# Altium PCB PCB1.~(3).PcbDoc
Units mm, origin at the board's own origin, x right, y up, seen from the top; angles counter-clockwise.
Board outline 152.4 x 101.6 mm, 2 copper layers (Top Layer, Bottom Layer); 27 components, 22 nets, 77 pads, 0 vias.
Unrouted connection lines stored in the file: 50.
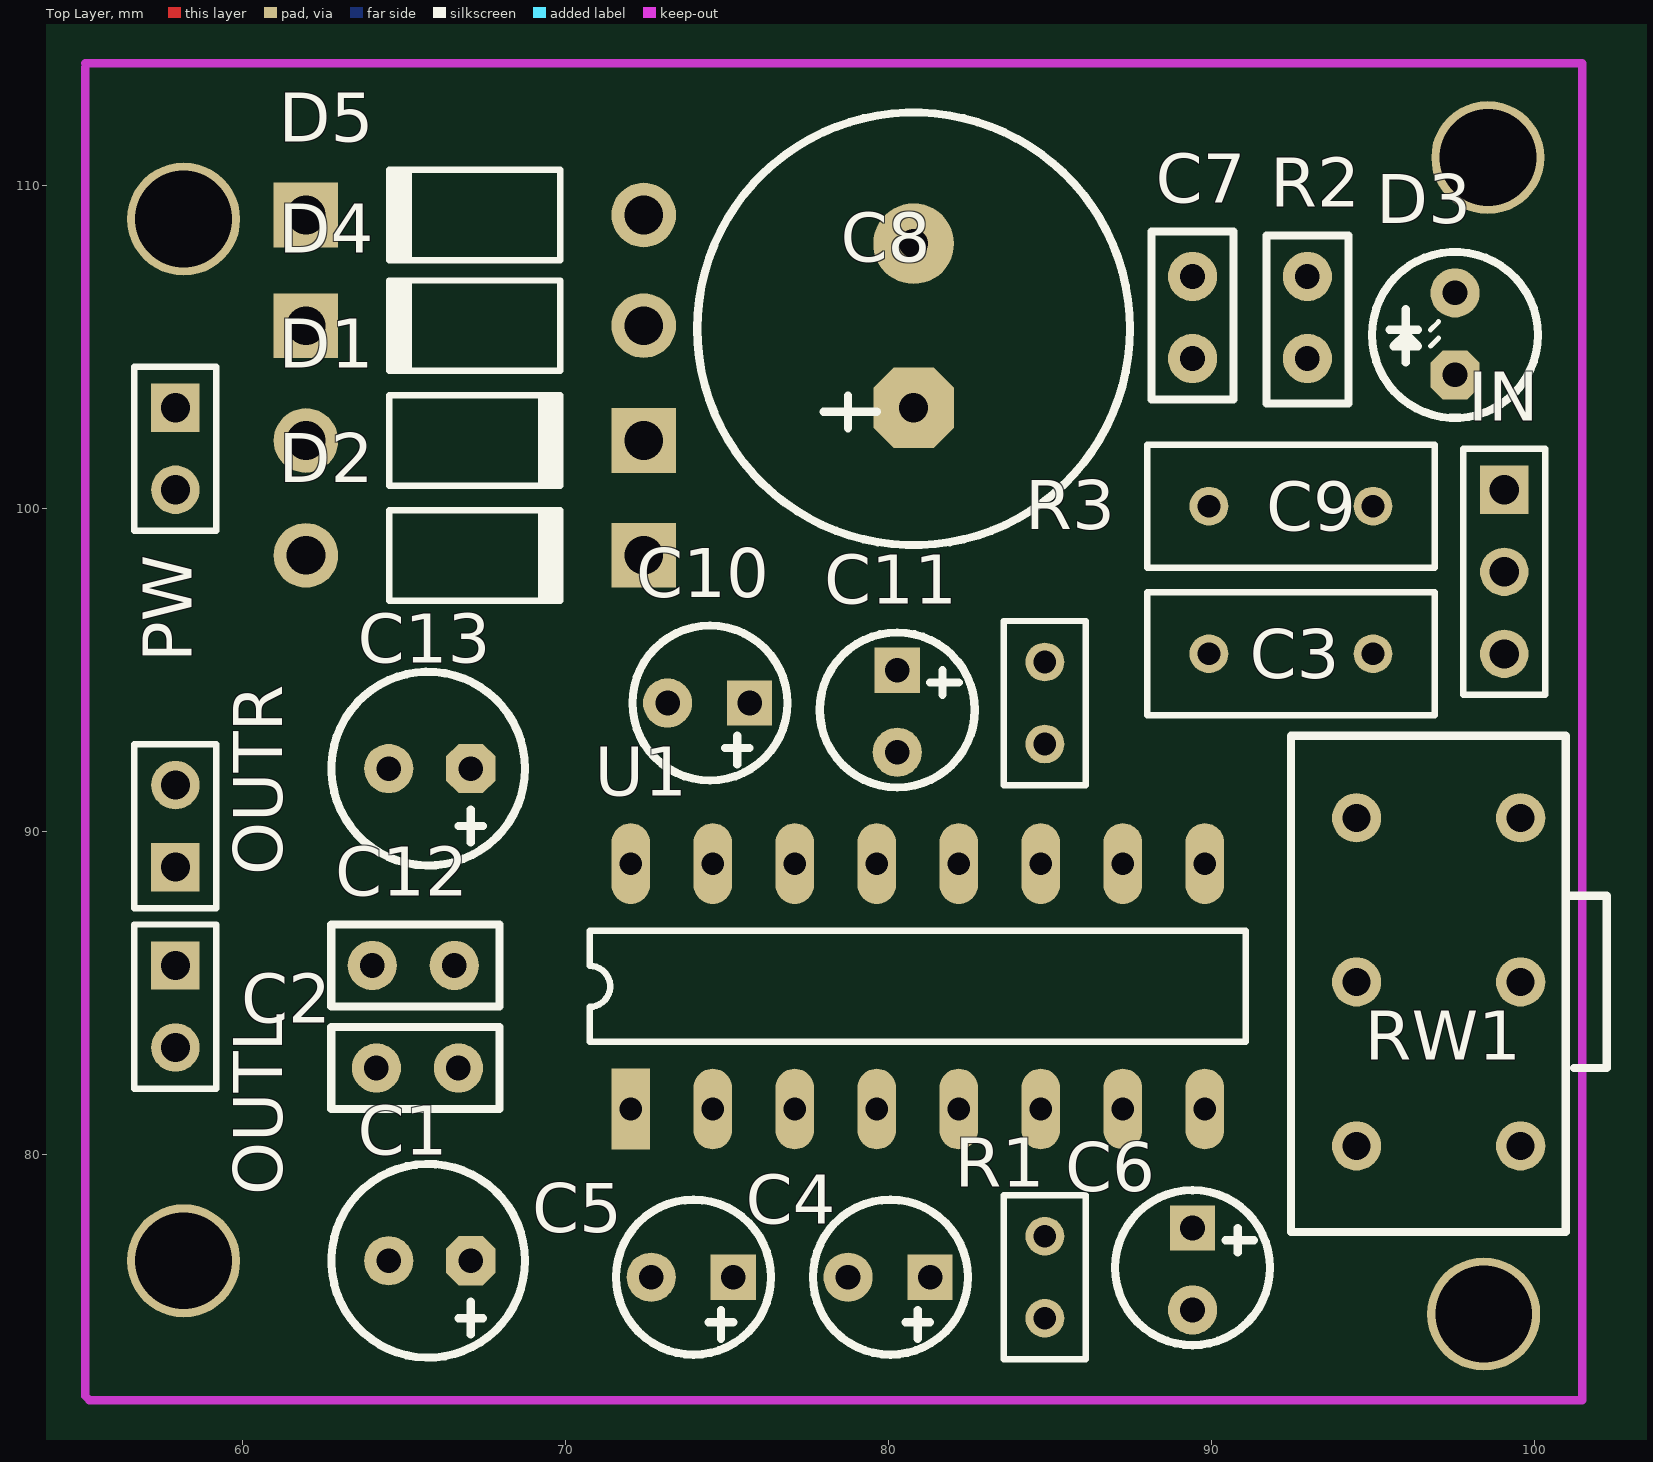
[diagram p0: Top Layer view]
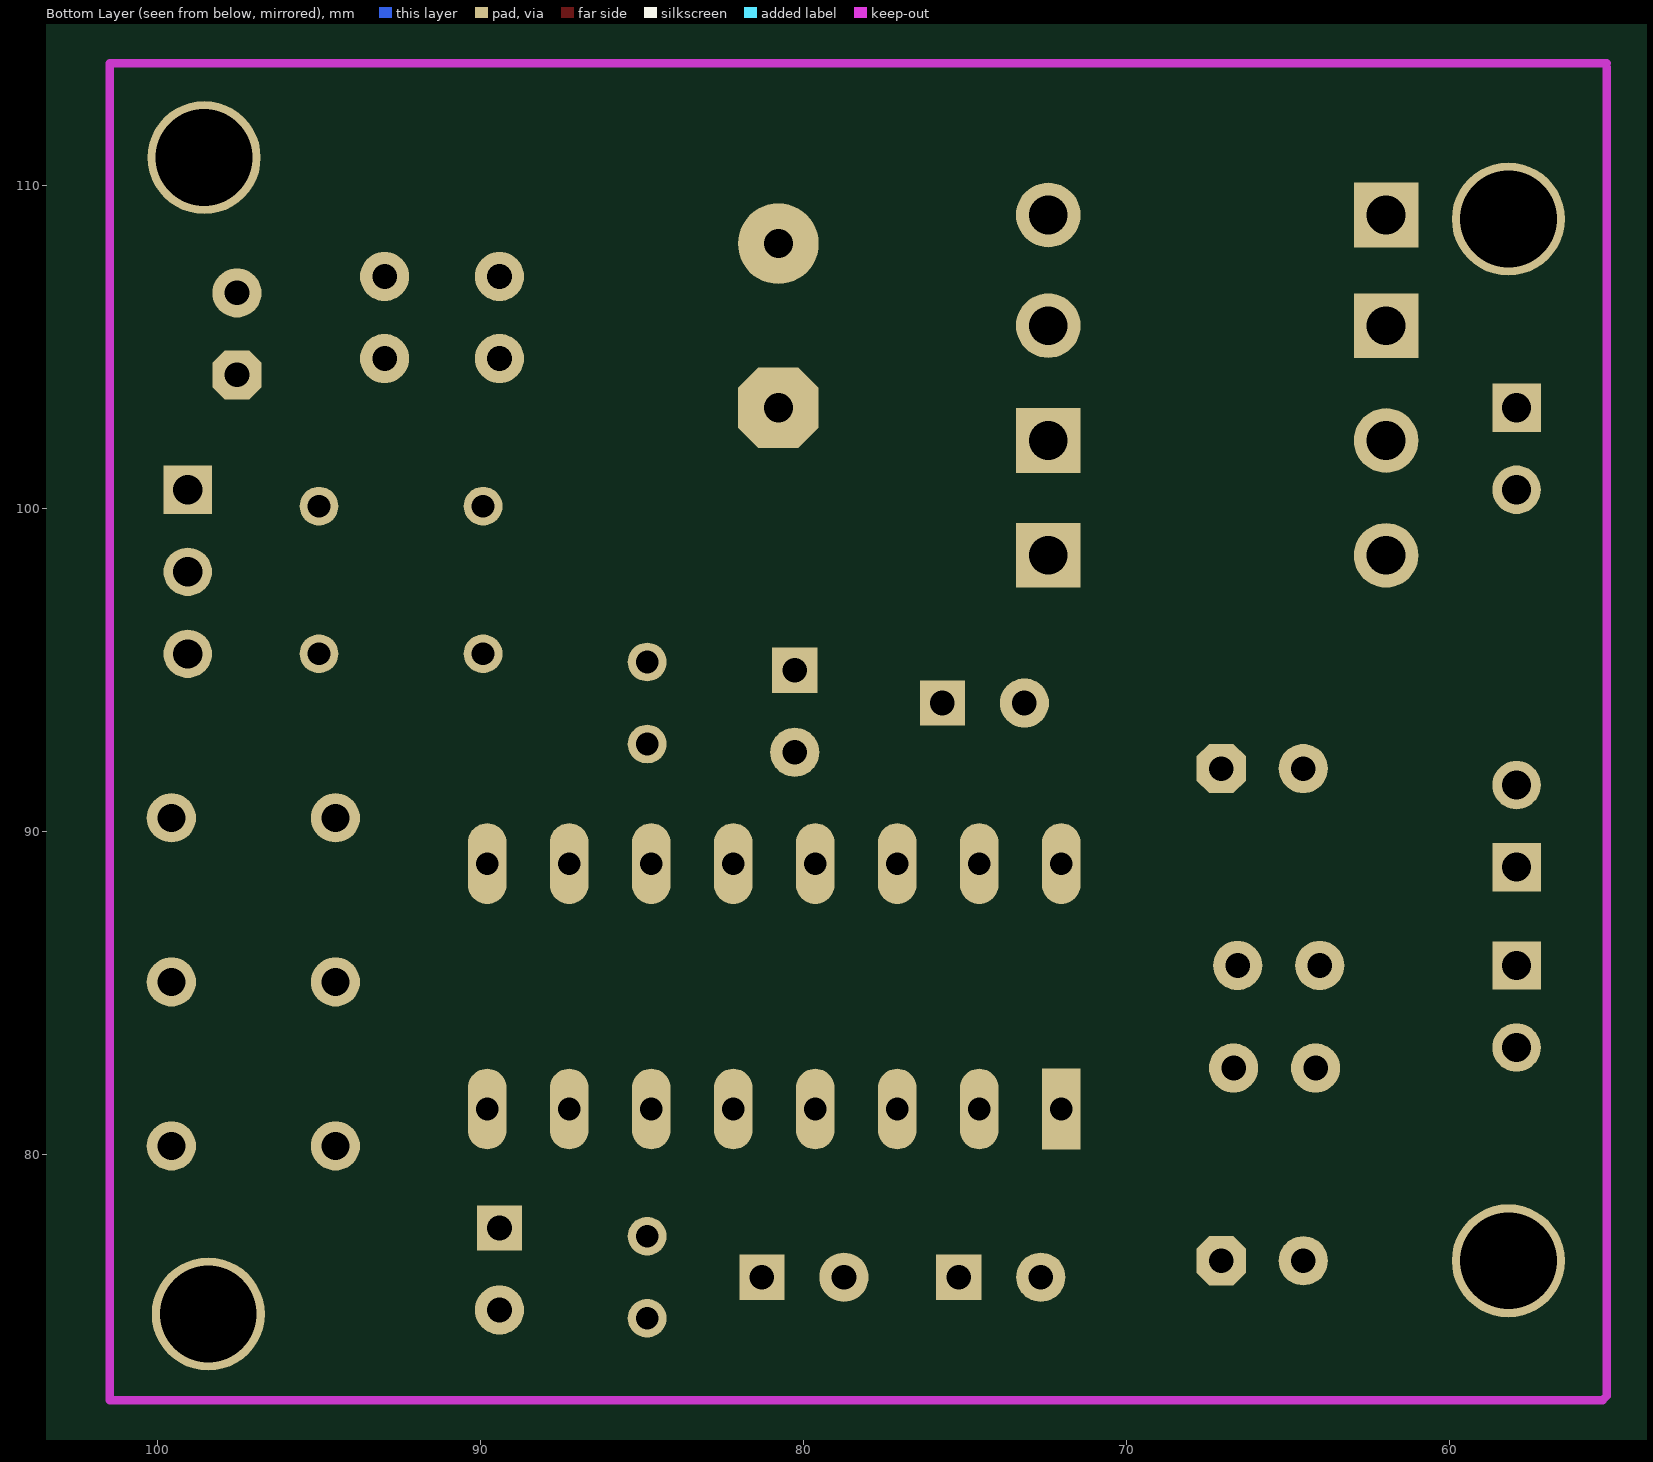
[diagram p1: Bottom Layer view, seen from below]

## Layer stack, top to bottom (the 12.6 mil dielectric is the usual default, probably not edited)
Top Layer: signal copper 0.0356
Dielectric: dielectric 0.32, FR-4, Dk 4.8
Bottom Layer: signal copper 0.0356

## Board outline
25.4,25.4 177.8,25.4 177.8,127 25.4,127

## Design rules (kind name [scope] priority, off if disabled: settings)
Clearance [All] p1: gap=0.254
PolygonConnect [All] p1: connectstyle=Relief reliefconductorwidth=0.254 reliefentries=4 polygonreliefangle="90 Angle"
RoutingVias [All] p1: holewidth=0.711 width=1.27 viastyle="Through Hole" minholewidth=0.711 minwidth=1.27 maxholewidth=0.711 maxwidth=1.27
SilkscreenOverComponentPads [All] p1: minsilkscreentomaskgap=0.254
SolderMaskExpansion [All] p1: expansion=0.102
Width [All] p1: maxlimit=0.254 minlimit=0.254 preferedwidth=0.254
27 further rules are at their usual default settings.

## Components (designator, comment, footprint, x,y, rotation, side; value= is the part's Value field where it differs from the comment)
C1 "470u" CF0.1-6.5 67.056,76.708 r180 top
C2 "0.1u" RAD0.1 64.135,82.677 r0 top
C3 "0.22" RAD-0.2 92.456,95.504 r180 top
C4 "100u" CF0.1 81.28,76.2 r180 top
C5 "100u" CF0.1 75.184,76.2 r180 top
C6 "100u" CF0.1 89.408,77.724 r270 top
C7 "Cap" RAD0.1 89.408,107.188 r270 top
C8 "CF" CF0.2-13 80.772,103.124 r90 top
C9 "0.22" RAD-0.2 92.456,100.076 r180 top
C10 "100u" CF0.1 75.692,93.98 r180 top
C11 "100u" CF0.1 80.264,94.996 r270 top
C12 "0.1u" RAD0.1 66.548,85.852 r180 top
C13 "470u" CF0.1-6.5 67.056,91.948 r180 top
D1 "Diode 1N4007" DIO10.46-5.3x2.8 67.183,102.108 r0 top
D2 "Diode 1N4007" DIO10.46-5.3x2.8 67.183,98.552 r0 top
D3 "LED0" LED 97.536,104.14 r90 top
D4 "Diode 1N4007" DIO10.46-5.3x2.8 67.183,105.664 r180 top
D5 "Diode 1N4007" DIO10.46-5.3x2.8 67.183,109.093 r180 top
IN "" HDR1X3 99.06,100.584 r270 top
OUTL "Header 2" HDR1X2 57.912,85.852 r270 top
OUTR "Header 2" HDR1X2 57.912,88.9 r90 top
PW "Header 2" HDR1X2 57.912,103.124 r270 top
R1 "1k" RAD-0.1 84.836,76.2 r270 top
R2 "Res" RAD0.1 92.964,104.648 r90 top
R3 "1k" RAD-0.1 84.836,93.98 r270 top
RW1 "RW" RW 99.568,80.264 r180 top
U1 "TEA2025" DIP16 72.009,81.407 r90 top

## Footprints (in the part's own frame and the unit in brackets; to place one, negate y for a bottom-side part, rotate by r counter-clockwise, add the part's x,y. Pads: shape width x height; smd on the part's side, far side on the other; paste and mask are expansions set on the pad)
CF0.1 [mil]
  rect 55.12x55.12 hole 30: 1(0,0)
  round 60 hole 30: 2(100,0)
  silkscreen extent -46,-94 143,94
CF0.1-6.5 [mil]
  oct 60x60 hole 30: 1(0,0)
  round 60 hole 30: 2(100,0)
  silkscreen extent -66,-118 170,118
CF0.2-13 [mm]
  oct 2.5x2.5 hole 0.9: 1(0,0)
  round 2.5 hole 0.9: 2(5.08,0)
  silkscreen extent -4.25,-6.7 9.14,6.7
DIO10.46-5.3x2.8 [mm] "Diode, Axial; Body 5.2 x 2.7 mm (LxDia. max), Lead Dia. 0.86 mm (max)"
  round 2 hole 1.2: 1(-5.23,0)
  rect 2x2 hole 1.2: 2(5.23,0)
  silkscreen extent -2.65,-1.4 2.75,1.4
DIP16 [mm]
  rect 2.5x1.2 hole 0.7: 1(0,0)
  oval 2.5x1.2 hole 0.7: 2(0,-2.54) 3(0,-5.08) 4(0,-7.62) 5(0,-10.16) 6(0,-12.7) 7(0,-15.24) 8(0,-17.78) 9(7.6,-17.78) 10(7.6,-15.24) 11(7.6,-12.7) 12(7.6,-10.16) 13(7.6,-7.62) 14(7.6,-5.08) 15(7.6,-2.54) 16(7.6,0)
  silkscreen extent 2.08,-19.05 5.52,1.27
HDR1X2 [mm] "Connector; Header; 2 Position"
  rect 1.5x1.5 hole 0.9: 1(0,0)
  round 1.5 hole 0.9: 2(2.54,0)
  silkscreen extent -1.27,-1.27 3.81,1.27
HDR1X3 [mm] "Connector; Header; 3 Position"
  rect 1.5x1.5 hole 0.9: 1(0,0)
  round 1.5 hole 0.9: 2(2.54,0) 3(5.08,0)
  silkscreen extent -1.27,-1.27 6.35,1.27
LED [mil]
  oct 60x60 hole 30: 1(0,0)
  round 60 hole 30: 2(100,0)
  silkscreen extent -52,-101 150,101
RAD0.1 [mil]
  round 60 hole 30: 1(0,0) 2(100,0)
  silkscreen extent -55,-50 150,50
RAD-0.1 [mm] "Radial Cap, Thru-Hole; 2 Leads; 0.1 in Pin Spacing"
  round 1.2 hole 0.7: 1(-1.27,0) 2(1.27,0)
  silkscreen extent -2.54,-1.27 2.54,1.27
RAD-0.2 [mm] "Radial Cap, Thru-Hole; 2 Leads; 0.2 in Pin Spacing"
  round 1.2 hole 0.7: 1(-2.54,0) 2(2.54,0)
  silkscreen extent -4.44,-1.91 4.44,1.91
RW [mil]
  round 60 hole 33.94: 1(0,0) 2(0,-200) 3(0,-400) 4(200,0) 5(200,-200) 6(200,-400)
  silkscreen extent -105,-500 280,105

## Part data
C1 C13: library part CF
C2 C3 C9 C12: library part Cap
C4 C5 C6 C10 C11: library part "Cap Pol"
D1 D2 D4 D5: "1 Amp General Purpose Rectifier"
IN: library part "Header 3H", "Header, 3-Pin, Right Angle"
OUTL OUTR PW: "Header, 2-Pin"
R1 R3: library part Res, "Resistor"
R2: "Resistor"

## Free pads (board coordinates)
  round 3.5 hole 3: 0(98.552,110.871) 1(58.166,108.966) 2(58.166,76.708) 3(98.425,75.057)

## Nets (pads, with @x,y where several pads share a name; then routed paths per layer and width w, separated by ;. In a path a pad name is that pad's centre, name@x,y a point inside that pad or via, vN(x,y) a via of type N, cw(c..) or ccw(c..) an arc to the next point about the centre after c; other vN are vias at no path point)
GND: C2.1 C4.2 C6.2 C7.1 C8.2 C11.2 C12.2 D4.1 D5.1 IN.2 OUTL.1 OUTR.1 R2.1 RW1.1 RW1.4 U1.4 U1.5 U1.9 U1.12 U1.13
NetC1_1: C1.1 C2.2 C5.2 U1.2
NetC1_2: C1.2 OUTL.2
NetC3_1: C3.1 RW1.2
NetC3_2: C3.2 U1.7
NetC4_1: C4.1 R1.2
NetC5_1: C5.1 U1.3
NetC6_1: C6.1 U1.8
NetC9_1: C9.1 RW1.5
NetC9_2: C9.2 U1.10
NetC10_1: C10.1 U1.14
NetC10_2: C10.2 C12.1 C13.1 U1.15
NetC11_1: C11.1 R3.1
NetC13_2: C13.2 OUTR.2
NetD1_1: D1.1 D4.2 PW.1
NetD2_1: D2.1 D5.2 PW.2
NetD3_2: D3.2 R2.2
NetIN_1: IN.1 RW1.6
NetIN_3: IN.3 RW1.3
NetR1_1: R1.1 U1.6
NetR3_2: R3.2 U1.11
VCC: C7.2 C8.1 D1.2 D2.2 D3.1 U1.16
pads on no net: U1.1

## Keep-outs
Keep-Out Layer:
  lines w0.254: 55.118,113.665 55.118,72.517 55.245,72.39 101.473,72.39 101.473,113.792 55.118,113.792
